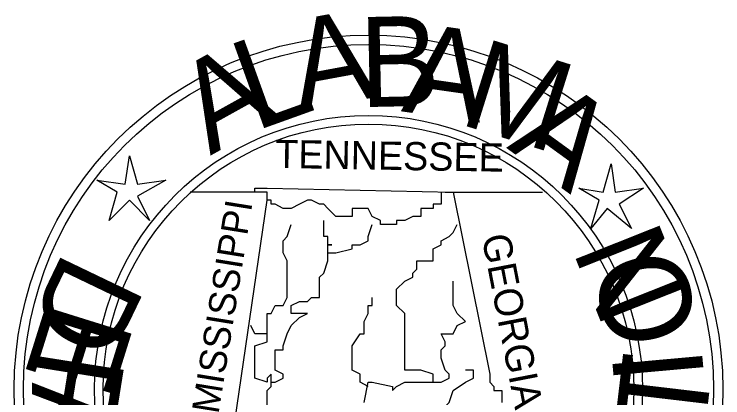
# Model space of a CAD drawing. Extents: x 515543 to 517243, y 660510 to 662861.
# Drawn here: x 516447.19 to 516493.18, y 661810.2 to 661835.12 of the extents above; entities that cross this region are included whole.
import ezdxf

# ---------------------------------------------------------------- set-up
doc = ezdxf.new("R2010")
doc.units = 0
doc.layers.add('great seal', color=7, linetype='Continuous')

msp = doc.modelspace()

# ---------------------------------------------------------------- linework, layer by layer
at = {"layer": 'great seal'}
for p, q in [((516463.597, 661823.559), (516458.604, 661823.559)), ((516463.597, 661823.559), (516458.604, 661823.559)), ((516463.597, 661823.559), (516458.604, 661823.559)), ((516475.158, 661823.559), (516481.465, 661823.559)), ((516475.158, 661823.559), (516481.465, 661823.559)), ((516475.158, 661823.559), (516481.465, 661823.559)), ((516470.166, 661810.946), (516470.166, 661810.946)), ((516470.166, 661810.946), (516470.166, 661810.946)), ((516470.166, 661810.946), (516470.166, 661810.946)), ((516470.166, 661810.946), (516470.166, 661810.946)), ((516470.166, 661810.946), (516470.166, 661810.946)), ((516470.166, 661810.946), (516470.166, 661810.946))]:
    msp.add_line(p, q, dxfattribs=at)
for points in [[(516454.663, 661825.924), (516455.188, 661824.084), (516457.028, 661824.347), (516455.188, 661823.296), (516455.977, 661821.719), (516454.663, 661823.033), (516453.349, 661821.719), (516453.875, 661823.559), (516452.561, 661824.347), (516454.4, 661824.084)], [(516454.663, 661825.924), (516455.188, 661824.084), (516457.028, 661824.347), (516455.188, 661823.296), (516455.977, 661821.719), (516454.663, 661823.033), (516453.349, 661821.719), (516453.875, 661823.559), (516452.561, 661824.347), (516454.4, 661824.084)], [(516454.663, 661825.924), (516455.188, 661824.084), (516457.028, 661824.347), (516455.188, 661823.296), (516455.977, 661821.719), (516454.663, 661823.033), (516453.349, 661821.719), (516453.875, 661823.559), (516452.561, 661824.347), (516454.4, 661824.084)], [(516485.932, 661825.398), (516486.195, 661823.559), (516488.034, 661823.822), (516486.457, 661822.77), (516487.246, 661821.194), (516485.669, 661822.508), (516484.618, 661821.194), (516485.144, 661823.033), (516483.83, 661823.822), (516485.406, 661823.559)], [(516485.932, 661825.398), (516486.195, 661823.559), (516488.034, 661823.822), (516486.457, 661822.77), (516487.246, 661821.194), (516485.669, 661822.508), (516484.618, 661821.194), (516485.144, 661823.033), (516483.83, 661823.822), (516485.406, 661823.559)], [(516485.932, 661825.398), (516486.195, 661823.559), (516488.034, 661823.822), (516486.457, 661822.77), (516487.246, 661821.194), (516485.669, 661822.508), (516484.618, 661821.194), (516485.144, 661823.033), (516483.83, 661823.822), (516485.406, 661823.559)]]:
    msp.add_lwpolyline(points, close=True, dxfattribs=at)
for points in [[(516461.232, 661806.742), (516463.597, 661823.033), (516463.597, 661823.559), (516463.597, 661823.559), (516463.597, 661823.559), (516462.809, 661823.559), (516462.809, 661823.822), (516463.597, 661823.822), (516475.684, 661823.559), (516478.049, 661811.734), (516478.049, 661811.209), (516478.312, 661810.946), (516478.312, 661810.683), (516478.312, 661810.683), (516478.837, 661810.683), (516478.837, 661809.895)], [(516461.232, 661806.742), (516463.597, 661823.033), (516463.597, 661823.559), (516463.597, 661823.559), (516463.597, 661823.559), (516462.809, 661823.559), (516462.809, 661823.822), (516463.597, 661823.822), (516475.684, 661823.559), (516478.049, 661811.734), (516478.049, 661811.209), (516478.312, 661810.946), (516478.312, 661810.683), (516478.312, 661810.683), (516478.837, 661810.683), (516478.837, 661809.895)], [(516461.232, 661806.742), (516463.597, 661823.033), (516463.597, 661823.559), (516463.597, 661823.559), (516463.597, 661823.559), (516462.809, 661823.559), (516462.809, 661823.822), (516463.597, 661823.822), (516475.684, 661823.559), (516478.049, 661811.734), (516478.049, 661811.209), (516478.312, 661810.946), (516478.312, 661810.683), (516478.312, 661810.683), (516478.837, 661810.683), (516478.837, 661809.895)], [(516474.896, 661823.559), (516474.896, 661823.559), (516474.896, 661823.559), (516474.896, 661823.033), (516474.896, 661822.77), (516474.896, 661822.77), (516474.37, 661822.77), (516474.37, 661822.77), (516474.37, 661822.508), (516473.582, 661822.508), (516473.582, 661821.982), (516473.056, 661821.982), (516472.531, 661821.719), (516472.268, 661821.719), (516472.005, 661821.719), (516472.005, 661821.457), (516471.743, 661821.457), (516471.743, 661821.457), (516470.954, 661821.457), (516470.954, 661821.457), (516470.954, 661821.719), (516470.429, 661821.982), (516470.166, 661822.508), (516470.166, 661822.508), (516469.64, 661822.508), (516469.115, 661822.508), (516469.115, 661821.982), (516468.064, 661821.982), (516467.538, 661822.508), (516467.276, 661822.77), (516467.013, 661822.77), (516466.487, 661823.033), (516466.224, 661823.033), (516465.699, 661822.77), (516465.699, 661822.77), (516465.173, 661822.508), (516464.911, 661822.508), (516464.648, 661822.508), (516464.122, 661822.77), (516464.122, 661822.77), (516464.122, 661822.77), (516463.86, 661822.77), (516463.86, 661822.77), (516463.86, 661822.77), (516463.86, 661823.033), (516463.597, 661823.033), (516463.597, 661823.559), (516463.597, 661823.559), (516463.597, 661823.559)], [(516474.896, 661823.559), (516474.896, 661823.559), (516474.896, 661823.559), (516474.896, 661823.033), (516474.896, 661822.77), (516474.896, 661822.77), (516474.37, 661822.77), (516474.37, 661822.77), (516474.37, 661822.508), (516473.582, 661822.508), (516473.582, 661821.982), (516473.056, 661821.982), (516472.531, 661821.719), (516472.268, 661821.719), (516472.005, 661821.719), (516472.005, 661821.457), (516471.743, 661821.457), (516471.743, 661821.457), (516470.954, 661821.457), (516470.954, 661821.457), (516470.954, 661821.719), (516470.429, 661821.982), (516470.166, 661822.508), (516470.166, 661822.508), (516469.64, 661822.508), (516469.115, 661822.508), (516469.115, 661821.982), (516468.064, 661821.982), (516467.538, 661822.508), (516467.276, 661822.77), (516467.013, 661822.77), (516466.487, 661823.033), (516466.224, 661823.033), (516465.699, 661822.77), (516465.699, 661822.77), (516465.173, 661822.508), (516464.911, 661822.508), (516464.648, 661822.508), (516464.122, 661822.77), (516464.122, 661822.77), (516464.122, 661822.77), (516463.86, 661822.77), (516463.86, 661822.77), (516463.86, 661822.77), (516463.86, 661823.033), (516463.597, 661823.033), (516463.597, 661823.559), (516463.597, 661823.559), (516463.597, 661823.559)], [(516474.896, 661823.559), (516474.896, 661823.559), (516474.896, 661823.559), (516474.896, 661823.033), (516474.896, 661822.77), (516474.896, 661822.77), (516474.37, 661822.77), (516474.37, 661822.77), (516474.37, 661822.508), (516473.582, 661822.508), (516473.582, 661821.982), (516473.056, 661821.982), (516472.531, 661821.719), (516472.268, 661821.719), (516472.005, 661821.719), (516472.005, 661821.457), (516471.743, 661821.457), (516471.743, 661821.457), (516470.954, 661821.457), (516470.954, 661821.457), (516470.954, 661821.719), (516470.429, 661821.982), (516470.166, 661822.508), (516470.166, 661822.508), (516469.64, 661822.508), (516469.115, 661822.508), (516469.115, 661821.982), (516468.064, 661821.982), (516467.538, 661822.508), (516467.276, 661822.77), (516467.013, 661822.77), (516466.487, 661823.033), (516466.224, 661823.033), (516465.699, 661822.77), (516465.699, 661822.77), (516465.173, 661822.508), (516464.911, 661822.508), (516464.648, 661822.508), (516464.122, 661822.77), (516464.122, 661822.77), (516464.122, 661822.77), (516463.86, 661822.77), (516463.86, 661822.77), (516463.86, 661822.77), (516463.86, 661823.033), (516463.597, 661823.033), (516463.597, 661823.559), (516463.597, 661823.559), (516463.597, 661823.559)], [(516467.538, 661819.617), (516467.538, 661819.88), (516467.538, 661820.143), (516467.801, 661820.143), (516467.538, 661820.143), (516467.538, 661820.406), (516467.538, 661820.668), (516467.276, 661820.668), (516467.276, 661820.931), (516467.276, 661821.457), (516467.276, 661821.719)], [(516467.538, 661819.617), (516467.538, 661819.88), (516467.538, 661820.143), (516467.801, 661820.143), (516467.538, 661820.143), (516467.538, 661820.406), (516467.538, 661820.668), (516467.276, 661820.668), (516467.276, 661820.931), (516467.276, 661821.457), (516467.276, 661821.719)], [(516467.538, 661819.617), (516467.538, 661819.88), (516467.538, 661820.143), (516467.801, 661820.143), (516467.538, 661820.143), (516467.538, 661820.406), (516467.538, 661820.668), (516467.276, 661820.668), (516467.276, 661820.931), (516467.276, 661821.457), (516467.276, 661821.719)], [(516463.597, 661814.362), (516463.597, 661814.888), (516463.597, 661815.15), (516463.597, 661815.676), (516463.86, 661815.676), (516464.122, 661816.201), (516464.648, 661816.201), (516464.911, 661816.727), (516464.911, 661817.778), (516464.911, 661818.303), (516464.911, 661818.566), (516464.911, 661819.092), (516464.648, 661819.617), (516464.648, 661820.143), (516464.648, 661820.406), (516464.911, 661820.668), (516465.173, 661821.457)], [(516463.597, 661814.362), (516463.597, 661814.888), (516463.597, 661815.15), (516463.597, 661815.676), (516463.86, 661815.676), (516464.122, 661816.201), (516464.648, 661816.201), (516464.911, 661816.727), (516464.911, 661817.778), (516464.911, 661818.303), (516464.911, 661818.566), (516464.911, 661819.092), (516464.648, 661819.617), (516464.648, 661820.143), (516464.648, 661820.406), (516464.911, 661820.668), (516465.173, 661821.457)], [(516463.597, 661814.362), (516463.597, 661814.888), (516463.597, 661815.15), (516463.597, 661815.676), (516463.86, 661815.676), (516464.122, 661816.201), (516464.648, 661816.201), (516464.911, 661816.727), (516464.911, 661817.778), (516464.911, 661818.303), (516464.911, 661818.566), (516464.911, 661819.092), (516464.648, 661819.617), (516464.648, 661820.143), (516464.648, 661820.406), (516464.911, 661820.668), (516465.173, 661821.457)], [(516463.86, 661811.209), (516463.86, 661811.209), (516464.122, 661811.209), (516464.122, 661811.209), (516464.648, 661811.472), (516464.648, 661811.734), (516464.122, 661811.997), (516464.122, 661811.997), (516464.122, 661812.785), (516464.122, 661813.311), (516464.648, 661813.311), (516464.648, 661813.574), (516464.911, 661814.362), (516465.173, 661814.888), (516465.699, 661815.413), (516466.224, 661815.676), (516465.699, 661815.676), (516465.173, 661815.676), (516465.173, 661816.201), (516465.699, 661816.464), (516465.699, 661816.464), (516466.224, 661816.464), (516466.487, 661816.727), (516466.487, 661816.727), (516467.013, 661816.727), (516467.013, 661817.252), (516467.013, 661817.778), (516467.013, 661817.778), (516467.013, 661818.041), (516467.276, 661818.303), (516467.538, 661819.092), (516467.538, 661819.092), (516467.538, 661819.617), (516467.801, 661819.617), (516468.064, 661819.617), (516468.064, 661819.617), (516469.115, 661819.88), (516469.115, 661820.143), (516469.64, 661820.143), (516470.166, 661820.406), (516470.166, 661820.668), (516470.429, 661821.457)], [(516463.86, 661811.209), (516463.86, 661811.209), (516464.122, 661811.209), (516464.122, 661811.209), (516464.648, 661811.472), (516464.648, 661811.734), (516464.122, 661811.997), (516464.122, 661811.997), (516464.122, 661812.785), (516464.122, 661813.311), (516464.648, 661813.311), (516464.648, 661813.574), (516464.911, 661814.362), (516465.173, 661814.888), (516465.699, 661815.413), (516466.224, 661815.676), (516465.699, 661815.676), (516465.173, 661815.676), (516465.173, 661816.201), (516465.699, 661816.464), (516465.699, 661816.464), (516466.224, 661816.464), (516466.487, 661816.727), (516466.487, 661816.727), (516467.013, 661816.727), (516467.013, 661817.252), (516467.013, 661817.778), (516467.013, 661817.778), (516467.013, 661818.041), (516467.276, 661818.303), (516467.538, 661819.092), (516467.538, 661819.092), (516467.538, 661819.617), (516467.801, 661819.617), (516468.064, 661819.617), (516468.064, 661819.617), (516469.115, 661819.88), (516469.115, 661820.143), (516469.64, 661820.143), (516470.166, 661820.406), (516470.166, 661820.668), (516470.429, 661821.457)], [(516463.86, 661811.209), (516463.86, 661811.209), (516464.122, 661811.209), (516464.122, 661811.209), (516464.648, 661811.472), (516464.648, 661811.734), (516464.122, 661811.997), (516464.122, 661811.997), (516464.122, 661812.785), (516464.122, 661813.311), (516464.648, 661813.311), (516464.648, 661813.574), (516464.911, 661814.362), (516465.173, 661814.888), (516465.699, 661815.413), (516466.224, 661815.676), (516465.699, 661815.676), (516465.173, 661815.676), (516465.173, 661816.201), (516465.699, 661816.464), (516465.699, 661816.464), (516466.224, 661816.464), (516466.487, 661816.727), (516466.487, 661816.727), (516467.013, 661816.727), (516467.013, 661817.252), (516467.013, 661817.778), (516467.013, 661817.778), (516467.013, 661818.041), (516467.276, 661818.303), (516467.538, 661819.092), (516467.538, 661819.092), (516467.538, 661819.617), (516467.801, 661819.617), (516468.064, 661819.617), (516468.064, 661819.617), (516469.115, 661819.88), (516469.115, 661820.143), (516469.64, 661820.143), (516470.166, 661820.406), (516470.166, 661820.668), (516470.429, 661821.457)], [(516474.37, 661811.209), (516474.37, 661811.734), (516473.582, 661811.997), (516473.319, 661811.997), (516472.531, 661811.997), (516472.531, 661813.311), (516472.531, 661813.311), (516472.531, 661813.574), (516472.531, 661814.362), (516472.531, 661814.888), (516472.531, 661815.676), (516472.005, 661816.201), (516472.005, 661817.252), (516472.531, 661817.778), (516473.056, 661818.041), (516473.056, 661818.303), (516473.319, 661818.566), (516473.319, 661819.092), (516474.37, 661819.092), (516474.37, 661819.617), (516474.37, 661819.88), (516474.896, 661820.143), (516474.896, 661820.406), (516475.421, 661820.668), (516475.684, 661820.931), (516475.947, 661821.457)], [(516474.37, 661811.209), (516474.37, 661811.734), (516473.582, 661811.997), (516473.319, 661811.997), (516472.531, 661811.997), (516472.531, 661813.311), (516472.531, 661813.311), (516472.531, 661813.574), (516472.531, 661814.362), (516472.531, 661814.888), (516472.531, 661815.676), (516472.005, 661816.201), (516472.005, 661817.252), (516472.531, 661817.778), (516473.056, 661818.041), (516473.056, 661818.303), (516473.319, 661818.566), (516473.319, 661819.092), (516474.37, 661819.092), (516474.37, 661819.617), (516474.37, 661819.88), (516474.896, 661820.143), (516474.896, 661820.406), (516475.421, 661820.668), (516475.684, 661820.931), (516475.947, 661821.457)], [(516474.37, 661811.209), (516474.37, 661811.734), (516473.582, 661811.997), (516473.319, 661811.997), (516472.531, 661811.997), (516472.531, 661813.311), (516472.531, 661813.311), (516472.531, 661813.574), (516472.531, 661814.362), (516472.531, 661814.888), (516472.531, 661815.676), (516472.005, 661816.201), (516472.005, 661817.252), (516472.531, 661817.778), (516473.056, 661818.041), (516473.056, 661818.303), (516473.319, 661818.566), (516473.319, 661819.092), (516474.37, 661819.092), (516474.37, 661819.617), (516474.37, 661819.88), (516474.896, 661820.143), (516474.896, 661820.406), (516475.421, 661820.668), (516475.684, 661820.931), (516475.947, 661821.457)], [(516469.903, 661809.895), (516470.166, 661811.209), (516470.429, 661811.209), (516471.743, 661810.946), (516471.743, 661810.683), (516472.005, 661810.946), (516472.531, 661811.209), (516473.319, 661811.209), (516474.37, 661811.209), (516474.896, 661811.209), (516475.421, 661811.472), (516475.421, 661811.734), (516475.158, 661811.997), (516475.158, 661811.997), (516474.896, 661812.785), (516474.896, 661813.311), (516475.158, 661813.574), (516475.158, 661813.836), (516474.896, 661814.362), (516475.684, 661814.362), (516475.947, 661814.888), (516476.472, 661815.15), (516475.947, 661815.676), (516475.947, 661815.676), (516475.684, 661816.201), (516475.684, 661816.727), (516475.684, 661817.778)], [(516469.903, 661809.895), (516470.166, 661811.209), (516470.429, 661811.209), (516471.743, 661810.946), (516471.743, 661810.683), (516472.005, 661810.946), (516472.531, 661811.209), (516473.319, 661811.209), (516474.37, 661811.209), (516474.896, 661811.209), (516475.421, 661811.472), (516475.421, 661811.734), (516475.158, 661811.997), (516475.158, 661811.997), (516474.896, 661812.785), (516474.896, 661813.311), (516475.158, 661813.574), (516475.158, 661813.836), (516474.896, 661814.362), (516475.684, 661814.362), (516475.947, 661814.888), (516476.472, 661815.15), (516475.947, 661815.676), (516475.947, 661815.676), (516475.684, 661816.201), (516475.684, 661816.727), (516475.684, 661817.778)], [(516469.903, 661809.895), (516470.166, 661811.209), (516470.429, 661811.209), (516471.743, 661810.946), (516471.743, 661810.683), (516472.005, 661810.946), (516472.531, 661811.209), (516473.319, 661811.209), (516474.37, 661811.209), (516474.896, 661811.209), (516475.421, 661811.472), (516475.421, 661811.734), (516475.158, 661811.997), (516475.158, 661811.997), (516474.896, 661812.785), (516474.896, 661813.311), (516475.158, 661813.574), (516475.158, 661813.836), (516474.896, 661814.362), (516475.684, 661814.362), (516475.947, 661814.888), (516476.472, 661815.15), (516475.947, 661815.676), (516475.947, 661815.676), (516475.684, 661816.201), (516475.684, 661816.727), (516475.684, 661817.778)], [(516470.166, 661810.946), (516469.64, 661811.209), (516469.64, 661811.472), (516469.64, 661811.734), (516469.115, 661811.997), (516469.115, 661812.785), (516469.115, 661813.311), (516469.115, 661813.574), (516469.115, 661813.574), (516469.64, 661814.362), (516469.903, 661814.362), (516469.903, 661815.15), (516470.166, 661815.676), (516470.166, 661815.676), (516470.166, 661816.201), (516470.429, 661816.201), (516470.429, 661816.727)], [(516470.166, 661810.946), (516469.64, 661811.209), (516469.64, 661811.472), (516469.64, 661811.734), (516469.115, 661811.997), (516469.115, 661812.785), (516469.115, 661813.311), (516469.115, 661813.574), (516469.115, 661813.574), (516469.64, 661814.362), (516469.903, 661814.362), (516469.903, 661815.15), (516470.166, 661815.676), (516470.166, 661815.676), (516470.166, 661816.201), (516470.429, 661816.201), (516470.429, 661816.727)], [(516470.166, 661810.946), (516469.64, 661811.209), (516469.64, 661811.472), (516469.64, 661811.734), (516469.115, 661811.997), (516469.115, 661812.785), (516469.115, 661813.311), (516469.115, 661813.574), (516469.115, 661813.574), (516469.64, 661814.362), (516469.903, 661814.362), (516469.903, 661815.15), (516470.166, 661815.676), (516470.166, 661815.676), (516470.166, 661816.201), (516470.429, 661816.201), (516470.429, 661816.727)], [(516463.597, 661809.632), (516463.597, 661810.683), (516463.597, 661810.683), (516463.86, 661810.946), (516463.86, 661811.209), (516463.86, 661811.734), (516463.597, 661811.472), (516463.597, 661811.209), (516462.809, 661811.472), (516462.809, 661811.734), (516462.809, 661811.997), (516462.809, 661811.997), (516462.809, 661813.311), (516462.809, 661813.311), (516462.809, 661813.574), (516463.597, 661813.836), (516463.597, 661814.362), (516462.809, 661814.362), (516462.546, 661814.888), (516462.546, 661814.888)], [(516463.597, 661809.632), (516463.597, 661810.683), (516463.597, 661810.683), (516463.86, 661810.946), (516463.86, 661811.209), (516463.86, 661811.734), (516463.597, 661811.472), (516463.597, 661811.209), (516462.809, 661811.472), (516462.809, 661811.734), (516462.809, 661811.997), (516462.809, 661811.997), (516462.809, 661813.311), (516462.809, 661813.311), (516462.809, 661813.574), (516463.597, 661813.836), (516463.597, 661814.362), (516462.809, 661814.362), (516462.546, 661814.888), (516462.546, 661814.888)], [(516463.597, 661809.632), (516463.597, 661810.683), (516463.597, 661810.683), (516463.86, 661810.946), (516463.86, 661811.209), (516463.86, 661811.734), (516463.597, 661811.472), (516463.597, 661811.209), (516462.809, 661811.472), (516462.809, 661811.734), (516462.809, 661811.997), (516462.809, 661811.997), (516462.809, 661813.311), (516462.809, 661813.311), (516462.809, 661813.574), (516463.597, 661813.836), (516463.597, 661814.362), (516462.809, 661814.362), (516462.546, 661814.888), (516462.546, 661814.888)], [(516471.743, 661804.114), (516471.743, 661804.114), (516471.743, 661804.903), (516472.005, 661805.165), (516472.005, 661805.428), (516472.005, 661805.954), (516472.268, 661805.954), (516472.531, 661806.479), (516473.319, 661806.742), (516473.582, 661807.267), (516474.37, 661807.267), (516474.37, 661807.793), (516474.896, 661808.844), (516474.896, 661809.37), (516474.896, 661809.37), (516474.896, 661809.632), (516475.158, 661809.632), (516475.421, 661809.895), (516475.684, 661810.683), (516476.472, 661811.209), (516476.998, 661811.472), (516476.998, 661811.734), (516476.998, 661811.997), (516476.472, 661811.997)], [(516471.743, 661804.114), (516471.743, 661804.114), (516471.743, 661804.903), (516472.005, 661805.165), (516472.005, 661805.428), (516472.005, 661805.954), (516472.268, 661805.954), (516472.531, 661806.479), (516473.319, 661806.742), (516473.582, 661807.267), (516474.37, 661807.267), (516474.37, 661807.793), (516474.896, 661808.844), (516474.896, 661809.37), (516474.896, 661809.37), (516474.896, 661809.632), (516475.158, 661809.632), (516475.421, 661809.895), (516475.684, 661810.683), (516476.472, 661811.209), (516476.998, 661811.472), (516476.998, 661811.734), (516476.998, 661811.997), (516476.472, 661811.997)], [(516471.743, 661804.114), (516471.743, 661804.114), (516471.743, 661804.903), (516472.005, 661805.165), (516472.005, 661805.428), (516472.005, 661805.954), (516472.268, 661805.954), (516472.531, 661806.479), (516473.319, 661806.742), (516473.582, 661807.267), (516474.37, 661807.267), (516474.37, 661807.793), (516474.896, 661808.844), (516474.896, 661809.37), (516474.896, 661809.37), (516474.896, 661809.632), (516475.158, 661809.632), (516475.421, 661809.895), (516475.684, 661810.683), (516476.472, 661811.209), (516476.998, 661811.472), (516476.998, 661811.734), (516476.998, 661811.997), (516476.472, 661811.997)]]:
    msp.add_lwpolyline(points, dxfattribs=at)
for radius in [22.994, 22.994, 22.994, 22.389, 22.389, 22.389, 17.779, 17.779, 17.779, 17.222, 17.222, 17.222]:
    msp.add_circle((516470.184, 661810.762), radius, dxfattribs=at)

# ---------------------------------------------------------------- texts
for s, height, rotation, p in [('A', 5.851, 10.4972, (516465.699, 661828.814)), ('A', 5.851, 10.4972, (516465.699, 661828.814)), ('A', 5.851, 10.4972, (516465.699, 661828.814)), ('B', 5.848, 1.1955, (516469.64, 661829.077)), ('B', 5.848, 1.1955, (516469.64, 661829.077)), ('B', 5.848, 1.1955, (516469.64, 661829.077)), ('A', 5.848, 351.8938, (516472.268, 661828.814)), ('A', 5.848, 351.8938, (516472.268, 661828.814)), ('A', 5.848, 351.8938, (516472.268, 661828.814)), ('L', 5.851, 19.7988, (516462.809, 661827.5)), ('L', 5.851, 19.7988, (516462.809, 661827.5)), ('L', 5.851, 19.7988, (516462.809, 661827.5)), ('M', 5.851, 342.5921, (516475.947, 661828.026)), ('A', 5.851, 29.1005, (516459.918, 661825.924)), ('A', 5.851, 29.1005, (516459.918, 661825.924)), ('A', 5.851, 29.1005, (516459.918, 661825.924)), ('A', 5.848, 323.9887, (516479.1, 661826.449)), ('A', 5.848, 323.9887, (516479.1, 661826.449)), ('A', 5.848, 323.9887, (516479.1, 661826.449)), ('TENNESSEE', 1.8304, 359.041, (516464.122, 661825.135)), ('TENNESSEE', 1.8304, 359.041, (516464.122, 661825.135)), ('TENNESSEE', 1.8304, 359.041, (516464.122, 661825.135)), ('MISSISSIPPI', 1.75474, 80.8531, (516460.444, 661809.107)), ('MISSISSIPPI', 1.75474, 80.8531, (516460.444, 661809.107)), ('MISSISSIPPI', 1.75474, 80.8531, (516460.444, 661809.107)), ('N', 5.851, 111.721, (516490.924, 661816.727)), ('N', 5.851, 111.721, (516490.924, 661816.727)), ('N', 5.851, 111.721, (516490.924, 661816.727)), ('GEORGIA', 1.8446, 280.9296, (516477.523, 661820.668)), ('GEORGIA', 1.8446, 280.9296, (516477.523, 661820.668)), ('GEORGIA', 1.8446, 280.9296, (516477.523, 661820.668)), ('D', 5.851, 244.3352, (516450.459, 661819.88)), ('D', 5.851, 244.3352, (516450.459, 661819.88)), ('D', 5.851, 244.3352, (516450.459, 661819.88)), ('O', 5.851, 103.4326, (516491.713, 661814.362)), ('O', 5.851, 103.4326, (516491.713, 661814.362)), ('O', 5.851, 103.4326, (516491.713, 661814.362)), ('E', 5.851, 252.6236, (516449.408, 661816.727)), ('E', 5.851, 252.6236, (516449.408, 661816.727)), ('E', 5.851, 252.6236, (516449.408, 661816.727)), ('P', 5.851, 260.912, (516448.619, 661813.574)), ('P', 5.851, 260.912, (516448.619, 661813.574)), ('P', 5.851, 260.912, (516448.619, 661813.574)), ('I', 5.851, 95.1442, (516491.975, 661811.472)), ('I', 5.851, 95.1442, (516491.975, 661811.472)), ('I', 5.851, 95.1442, (516491.975, 661811.472)), ('T', 5.851, 83.2565, (516491.975, 661807.793)), ('T', 5.851, 83.2565, (516491.975, 661807.793)), ('T', 5.851, 83.2565, (516491.975, 661807.793)), ('A', 5.851, 269.2004, (516448.357, 661811.209)), ('A', 5.851, 269.2004, (516448.357, 661811.209)), ('A', 5.851, 269.2004, (516448.357, 661811.209))]:
    msp.add_text(s, height=height, rotation=rotation, dxfattribs=at).set_placement(p)

doc.saveas('drawing.dxf')
